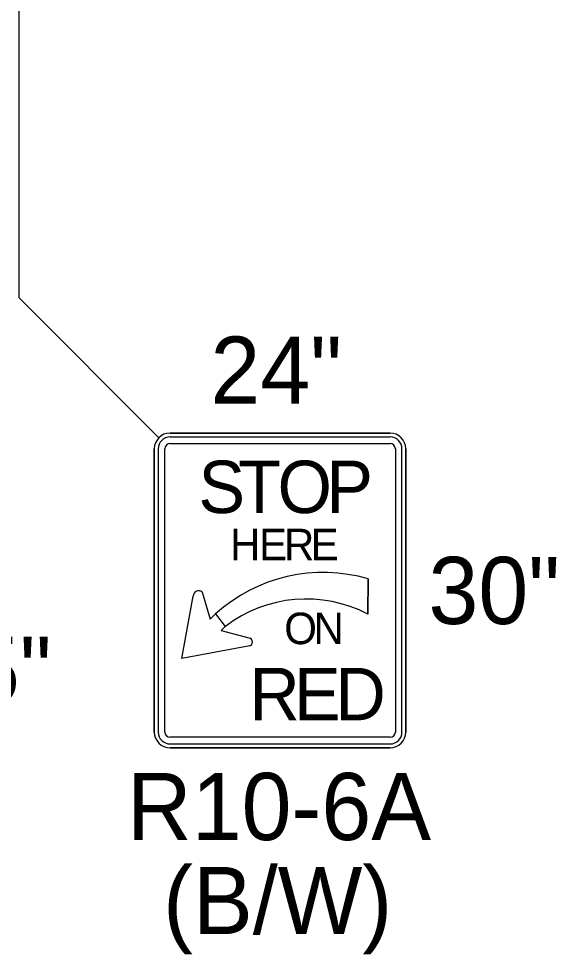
# Model space of a CAD drawing. Extents: x 99976 to 100136, y 99905 to 100011.
# Drawn here: x 100009.858 to 100010.435, y 99945.135 to 99946.138 of the extents above; entities that cross this region are included whole.
import ezdxf

# ---------------------------------------------------------------- set-up
doc = ezdxf.new("R2010")
doc.units = 0
doc.layers.add('TR_SN_ConstructionSigns', color=7, linetype='Continuous')
doc.layers.add('TR_WZ_WorkZoneDetails', color=7, linetype='Continuous')

msp = doc.modelspace()

# ---------------------------------------------------------------- linework, layer by layer
at = {"layer": 'TR_SN_ConstructionSigns'}
for p, q in [((100010.2562, 99945.6938), (100010.02, 99945.6938)), ((100010.02, 99945.6938), (100010.2562, 99945.6938)), ((100010.2562, 99945.6938), (100010.02, 99945.6938)), ((100010.02, 99945.6938), (100010.2562, 99945.6938)), ((100010.2562, 99945.6895), (100010.02, 99945.6895)), ((100010.0031, 99945.6769), (100010.0031, 99945.3731)), ((100010.0031, 99945.3731), (100010.0031, 99945.6769)), ((100010.0031, 99945.6769), (100010.0031, 99945.3731)), ((100010.0031, 99945.3731), (100010.0031, 99945.6769)), ((100010.0073, 99945.6769), (100010.0073, 99945.3731)), ((100010.0144, 99945.3731), (100010.0144, 99945.6769)), ((100010.02, 99945.6825), (100010.2562, 99945.6825)), ((100010.2619, 99945.6769), (100010.2619, 99945.3731)), ((100010.2689, 99945.3731), (100010.2689, 99945.6769)), ((100010.2731, 99945.3731), (100010.2731, 99945.6769)), ((100010.2731, 99945.6769), (100010.2731, 99945.3731)), ((100010.2731, 99945.3731), (100010.2731, 99945.6769)), ((100010.2731, 99945.6769), (100010.2731, 99945.3731)), ((100010.2326, 99945.5374), (100010.2323, 99945.4996)), ((100010.2323, 99945.4996), (100010.2326, 99945.5374)), ((100010.0326, 99945.4519), (100010.0449, 99945.5189)), ((100010.0546, 99945.5232), (100010.0631, 99945.4941)), ((100010.0631, 99945.4941), (100010.0688, 99945.4998)), ((100010.0688, 99945.4998), (100010.0793, 99945.4864)), ((100010.0688, 99945.4998), (100010.0793, 99945.4864)), ((100010.0793, 99945.4864), (100010.075, 99945.4821)), ((100010.075, 99945.4821), (100010.1058, 99945.4738)), ((100010.1057, 99945.4655), (100010.0326, 99945.4519)), ((100010.2562, 99945.3675), (100010.02, 99945.3675)), ((100010.02, 99945.3605), (100010.2562, 99945.3605)), ((100010.02, 99945.3563), (100010.2562, 99945.3563)), ((100010.2562, 99945.3563), (100010.02, 99945.3563)), ((100010.02, 99945.3563), (100010.2562, 99945.3563)), ((100010.2562, 99945.3563), (100010.02, 99945.3563))]:
    msp.add_line(p, q, dxfattribs=at)
for centre, radius, start, end in [((100010.02, 99945.6769), 0.0169, 90, 180), ((100010.02, 99945.6769), 0.0169, 90, 180), ((100010.02, 99945.6769), 0.0169, 90, 180), ((100010.02, 99945.6769), 0.0169, 90, 180), ((100010.02, 99945.6769), 0.0127, 90, 180), ((100010.2562, 99945.6769), 0.0169, 0, 90), ((100010.2562, 99945.6769), 0.0169, 0, 90), ((100010.2562, 99945.6769), 0.0169, 0, 90), ((100010.2562, 99945.6769), 0.0169, 0, 90), ((100010.2562, 99945.6769), 0.0127, 0, 90), ((100010.02, 99945.6769), 0.00562, 90, 180), ((100010.2562, 99945.6769), 0.00562, 0, 90), ((100010.1842, 99945.3725), 0.1718, 73.6434, 132.2131), ((100010.1842, 99945.3725), 0.1718, 73.6434, 132.2131), ((100010.1662, 99945.3731), 0.1427, 62.4149, 127.4769), ((100010.1662, 99945.3731), 0.1427, 62.4149, 127.4769), ((100010.02, 99945.3731), 0.0169, 180, 270), ((100010.02, 99945.3731), 0.0169, 180, 270), ((100010.02, 99945.3731), 0.0169, 180, 270), ((100010.02, 99945.3731), 0.0169, 180, 270), ((100010.02, 99945.3731), 0.0127, 180, 270), ((100010.02, 99945.3731), 0.00562, 180, 270), ((100010.2562, 99945.3731), 0.0169, 270, 0), ((100010.2562, 99945.3731), 0.0169, 270, 0), ((100010.2562, 99945.3731), 0.0169, 270, 0), ((100010.2562, 99945.3731), 0.0127, 270, 0), ((100010.2562, 99945.3731), 0.00562, 270, 0), ((100010.2562, 99945.3731), 0.0169, 270, 0)]:
    msp.add_arc(centre, radius, start, end, dxfattribs=at)
for centre, major_axis, ratio, start_param, end_param in [((100010.0507, 99945.519), (-0.00583, -0.00008), 0.989437, 3.962549, 6.283185), ((100010.1037, 99945.4697), (-0.00414, 0.00215), 0.999053, 2.490568, 4.712389)]:
    msp.add_ellipse(centre, major_axis=major_axis, ratio=ratio, start_param=start_param, end_param=end_param, dxfattribs=at)
at = {"layer": 'TR_WZ_WorkZoneDetails'}
for p, q in [((100009.8576, 99946.3347), (100009.8576, 99945.8393)), ((100009.8576, 99945.8393), (100010.008, 99945.6888))]:
    msp.add_line(p, q, dxfattribs=at)

# ---------------------------------------------------------------- texts
at = {"layer": 'TR_SN_ConstructionSigns'}
for s, p in [('24"', (100010.0633, 99945.7253)), ('30"', (100010.2973, 99945.489)), ('15"', (100009.7516, 99945.4035)), ('R10-6A', (100009.9737, 99945.2573)), ('(B/W)', (100010.0125, 99945.1565))]:
    msp.add_text(s, height=0.072, rotation=360, dxfattribs=at).set_placement(p)
for s, height, p in [('S', 0.0562, (100010.0504, 99945.608)), ('T', 0.0562, (100010.0931, 99945.608)), ('O', 0.0562, (100010.1353, 99945.608)), ('P', 0.0562, (100010.1876, 99945.608)), ('H', 0.0338, (100010.0844, 99945.5574)), ('E', 0.0338, (100010.1155, 99945.5574)), ('R', 0.0338, (100010.1422, 99945.5574)), ('E', 0.0338, (100010.1708, 99945.5574)), ('O', 0.0338, (100010.1425, 99945.4674)), ('N', 0.0338, (100010.1739, 99945.4674)), ('R', 0.0562, (100010.105, 99945.3858)), ('E', 0.0562, (100010.1529, 99945.3858)), ('D', 0.0562, (100010.1973, 99945.3858))]:
    msp.add_text(s, height=height, dxfattribs=at).set_placement(p)

doc.saveas('drawing.dxf')
